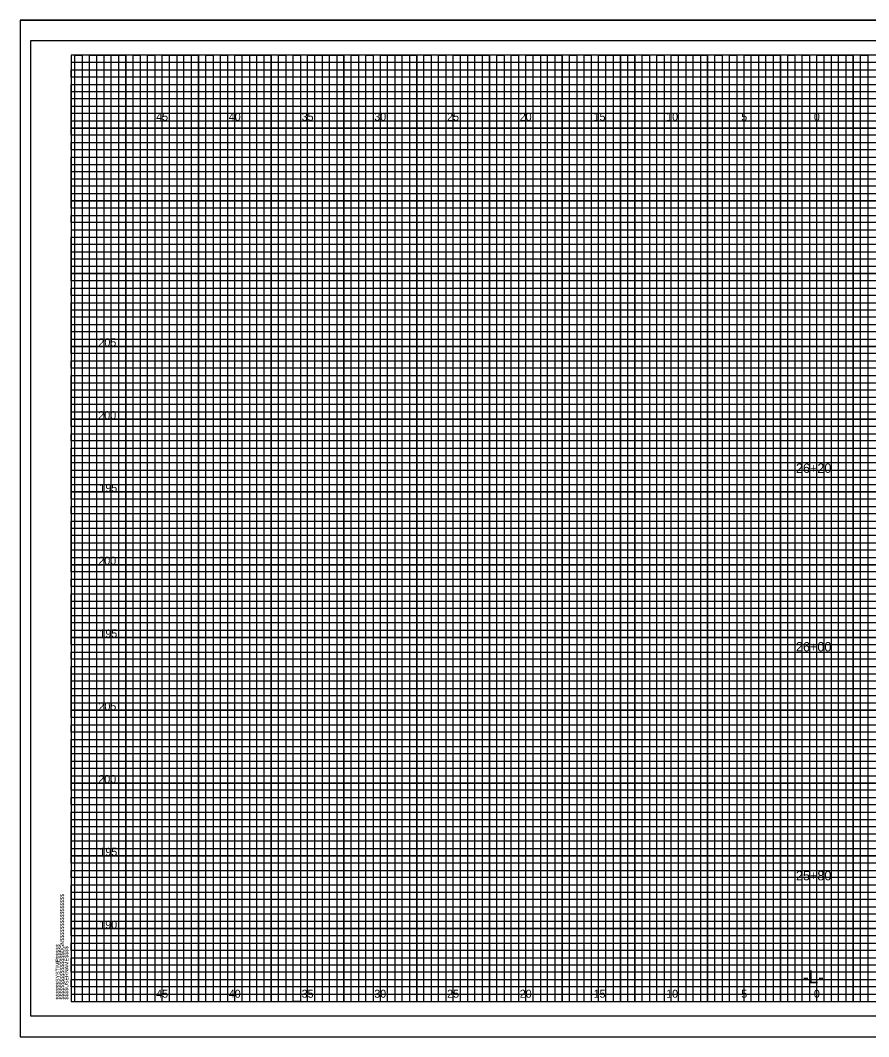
# Model space of a CAD drawing. Extents: x -4 to 103, y -2 to 6583.
# Drawn here: x -3.5 to 54.8, y 1555.7 to 1625.6 of the extents above; entities that cross this region are included whole.
import ezdxf

# ---------------------------------------------------------------- set-up
doc = ezdxf.new("R2010")
doc.units = 0
for name, color, linetype in [('Prop XS Alignment Label', 7, 'Continuous'), ('Prop XS Elevation Labels', 7, 'Continuous'), ('Prop XS Offset Labels', 7, 'Continuous'), ('Prop XS Station Labels', 7, 'Continuous'), ('Sheet Cross Section CELL', 7, 'Continuous'), ('Sheet Cross Section Grid Major CELL', 7, 'Continuous'), ('Sheet Cross Section Grid Middle CELL', 7, 'Continuous'), ('Sheet Cutting Line CELL', 7, 'Continuous'), ('Sheet DOT Grid CELL', 7, 'Continuous'), ('Sheet Plot Border Inside CELL', 7, 'Continuous'), ('Sheet Plot Border Outside CELL', 7, 'Continuous')]:
    doc.layers.add(name, color=color, linetype=linetype)

msp = doc.modelspace()

# ---------------------------------------------------------------- linework, layer by layer
at = {"layer": 'Sheet Cross Section CELL'}
msp.add_lwpolyline([(102.5, 1623.15), (0, 1623.15), (0, 1558.15), (102.5, 1558.15)], close=True, dxfattribs=at)
at = {"layer": 'Sheet Cross Section Grid Major CELL'}
for points in [[(1.25, 1558.15), (1.25, 1623.15), (3.75, 1623.15), (3.75, 1558.15), (6.25, 1558.15), (6.25, 1623.15), (8.75, 1623.15), (8.75, 1558.15), (11.25, 1558.15), (11.25, 1623.15), (13.75, 1623.15), (13.75, 1558.15), (16.25, 1558.15), (16.25, 1623.15), (18.75, 1623.15), (18.75, 1558.15), (21.25, 1558.15), (21.25, 1623.15), (23.75, 1623.15), (23.75, 1558.15), (26.25, 1558.15), (26.25, 1623.15), (28.75, 1623.15), (28.75, 1558.15), (31.25, 1558.15), (31.25, 1623.15), (33.75, 1623.15), (33.75, 1558.15), (36.25, 1558.15), (36.25, 1623.15), (38.75, 1623.15), (38.75, 1558.15), (41.25, 1558.15), (41.25, 1623.15), (43.75, 1623.15), (43.75, 1558.15), (46.25, 1558.15), (46.25, 1623.15), (48.75, 1623.15), (48.75, 1558.15), (51.25, 1558.15), (51.25, 1623.15), (53.75, 1623.15), (53.75, 1558.15)], [(102.5, 1618.15), (0, 1618.15), (0, 1620.65), (74.25, 1620.65)], [(102.5, 1613.15), (0, 1613.15), (0, 1615.65), (102.5, 1615.65)], [(102.5, 1608.15), (0, 1608.15), (0, 1610.65), (102.5, 1610.65)], [(102.5, 1603.15), (0, 1603.15), (0, 1605.65), (102.5, 1605.65)], [(102.5, 1598.15), (0, 1598.15), (0, 1600.65), (102.5, 1600.65)], [(102.5, 1593.15), (0, 1593.15), (0, 1595.65), (102.5, 1595.65)], [(102.5, 1588.15), (0, 1588.15), (0, 1590.65), (102.5, 1590.65)], [(102.5, 1583.15), (0, 1583.15), (0, 1585.65), (102.5, 1585.65)], [(102.5, 1578.15), (0, 1578.15), (0, 1580.65), (102.5, 1580.65)], [(102.5, 1573.15), (0, 1573.15), (0, 1575.65), (102.5, 1575.65)], [(102.5, 1568.15), (0, 1568.15), (0, 1570.65), (102.5, 1570.65)], [(102.5, 1563.15), (0, 1563.15), (0, 1565.65), (102.5, 1565.65)], [(0, 1560.65), (102.5, 1560.65)]]:
    msp.add_lwpolyline(points, dxfattribs=at)
at = {"layer": 'Sheet Cross Section Grid Middle CELL'}
for points in [[(0.25, 1558.15), (0.25, 1623.15), (0.75, 1623.15), (0.75, 1558.15), (1.75, 1558.15), (1.75, 1623.15), (2.25, 1623.15), (2.25, 1558.15), (2.75, 1558.15), (2.75, 1623.15), (3.25, 1623.15), (3.25, 1558.15), (4.25, 1558.15), (4.25, 1623.15), (4.75, 1623.15), (4.75, 1558.15), (5.25, 1558.15), (5.25, 1623.15), (5.75, 1623.15), (5.75, 1558.15), (6.75, 1558.15), (6.75, 1623.15), (7.25, 1623.15), (7.25, 1558.15), (7.75, 1558.15), (7.75, 1623.15), (8.25, 1623.15), (8.25, 1558.15), (9.25, 1558.15), (9.25, 1623.15), (9.75, 1623.15), (9.75, 1558.15), (10.25, 1558.15), (10.25, 1623.15), (10.75, 1623.15), (10.75, 1558.15), (11.75, 1558.15), (11.75, 1623.15), (12.25, 1623.15), (12.25, 1558.15), (12.75, 1558.15), (12.75, 1623.15), (13.25, 1623.15), (13.25, 1558.15), (14.25, 1558.15), (14.25, 1623.15), (14.75, 1623.15), (14.75, 1558.15), (15.75, 1558.15), (15.25, 1558.15), (15.25, 1623.15), (15.75, 1623.15), (15.75, 1558.15), (16.75, 1558.15), (16.75, 1623.15), (17.25, 1623.15), (17.25, 1558.15), (17.75, 1558.15), (17.75, 1623.15), (18.25, 1623.15), (18.25, 1558.15), (19.25, 1558.15), (19.25, 1623.15), (19.75, 1623.15), (19.75, 1558.15), (20.25, 1558.15), (20.25, 1623.15), (20.75, 1623.15), (20.75, 1558.15), (21.75, 1558.15), (21.75, 1623.15), (22.25, 1623.15), (22.25, 1558.15), (22.75, 1558.15), (22.75, 1623.15), (23.25, 1623.15), (23.25, 1558.15), (24.25, 1558.15), (24.25, 1623.15), (24.75, 1623.15), (24.75, 1558.15), (25.25, 1558.15), (25.25, 1623.15), (25.75, 1623.15), (25.75, 1558.15), (26.75, 1558.15), (26.75, 1623.15), (27.25, 1623.15), (27.25, 1558.15), (27.75, 1558.15), (27.75, 1623.15), (28.25, 1623.15), (28.25, 1558.15), (29.25, 1558.15), (29.25, 1623.15), (29.75, 1623.15), (29.75, 1558.15), (30.25, 1558.15), (30.25, 1623.15), (30.75, 1623.15), (30.75, 1558.15)], [(30.75, 1558.15), (31.75, 1558.15), (31.75, 1623.15), (32.25, 1623.15), (32.25, 1558.15), (32.75, 1558.15), (32.75, 1623.15), (33.25, 1623.15), (33.25, 1558.15), (34.25, 1558.15), (34.25, 1623.15), (34.75, 1623.15), (34.75, 1558.15), (35.25, 1558.15), (35.25, 1623.15), (35.75, 1623.15), (35.75, 1558.15), (36.75, 1558.15), (36.75, 1623.15), (37.25, 1623.15), (37.25, 1558.15), (37.75, 1558.15), (37.75, 1623.15), (37.75, 1558.15)], [(38.25, 1623.15), (38.25, 1558.15), (39.25, 1558.15), (39.25, 1623.15), (39.75, 1623.15), (39.75, 1558.15), (40.25, 1558.15), (40.25, 1623.15), (40.75, 1623.15), (40.75, 1558.15), (41.75, 1558.15), (41.75, 1623.15), (42.25, 1623.15), (42.25, 1558.15), (42.75, 1558.15), (42.75, 1623.15), (43.25, 1623.15), (43.25, 1558.15), (43.75, 1558.15), (44.25, 1558.15), (44.25, 1623.15), (44.75, 1623.15), (44.75, 1558.15), (45.25, 1558.15), (45.25, 1623.15), (45.75, 1623.15), (45.75, 1558.15), (46.75, 1558.15), (46.75, 1623.15), (47.25, 1623.15), (47.25, 1558.15), (47.75, 1558.15), (47.75, 1623.15), (48.25, 1623.15), (48.25, 1558.15), (49.25, 1558.15), (49.25, 1623.15), (49.75, 1623.15), (49.75, 1558.15), (50.25, 1558.15), (50.25, 1623.15), (50.75, 1623.15), (50.75, 1558.15), (51.75, 1558.15), (51.75, 1623.15), (52.25, 1623.15), (52.25, 1558.15), (52.75, 1558.15), (52.75, 1623.15), (53.25, 1623.15), (53.25, 1558.15), (54.25, 1558.15), (54.25, 1623.15), (54.75, 1623.15), (54.75, 1558.15), (55.25, 1558.15)], [(0, 1620.15), (0, 1621.15), (74.25, 1621.15), (74.25, 1621.65), (0, 1621.65), (0, 1622.15), (74.25, 1622.15), (74.25, 1622.65), (0, 1622.65)], [(102.5, 1620.15), (0, 1620.15)], [(102.5, 1619.15), (0, 1619.15), (0, 1619.65), (102.5, 1619.65)], [(102.5, 1617.65), (0, 1617.65), (0, 1618.65), (102.5, 1618.65)], [(102.5, 1616.65), (0, 1616.65), (0, 1617.15), (102.5, 1617.15)], [(102.5, 1615.15), (0, 1615.15), (0, 1616.15), (102.5, 1616.15)], [(102.5, 1614.15), (0, 1614.15), (0, 1614.65), (102.5, 1614.65)], [(102.5, 1612.65), (0, 1612.65), (0, 1613.65), (102.5, 1613.65)], [(102.5, 1611.65), (0, 1611.65), (0, 1612.15), (102.5, 1612.15)], [(0, 1611.15), (102.5, 1611.15)], [(102.5, 1610.15), (0, 1610.15)], [(102.5, 1609.15), (0, 1609.15), (0, 1609.65), (102.5, 1609.65)], [(102.5, 1607.65), (0, 1607.65), (0, 1608.65), (102.5, 1608.65)], [(102.5, 1606.65), (0, 1606.65), (0, 1607.15), (102.5, 1607.15)], [(102.5, 1605.15), (0, 1605.15), (0, 1606.15), (102.5, 1606.15)], [(102.5, 1604.15), (0, 1604.15), (0, 1604.65), (102.5, 1604.65)], [(102.5, 1602.65), (0, 1602.65), (0, 1603.65), (102.5, 1603.65)], [(102.5, 1601.65), (0, 1601.65), (0, 1602.15), (102.5, 1602.15)], [(102.5, 1600.15), (0, 1600.15), (0, 1601.15), (102.5, 1601.15)], [(102.5, 1599.15), (0, 1599.15), (0, 1599.65), (102.5, 1599.65)], [(102.5, 1597.65), (0, 1597.65), (0, 1598.65), (102.5, 1598.65)], [(102.5, 1596.65), (0, 1596.65), (0, 1597.15), (102.5, 1597.15)], [(102.5, 1595.15), (0, 1595.15), (0, 1596.15), (102.5, 1596.15)], [(102.5, 1594.15), (0, 1594.15), (0, 1594.65), (102.5, 1594.65)], [(102.5, 1592.65), (0, 1592.65), (0, 1593.65), (102.5, 1593.65)], [(102.5, 1591.65), (0, 1591.65), (0, 1592.15), (102.5, 1592.15)], [(102.5, 1590.15), (0, 1590.15), (0, 1591.15), (102.5, 1591.15)], [(102.5, 1589.15), (0, 1589.15), (0, 1589.65)], [(0, 1589.65), (102.5, 1589.65)], [(102.5, 1587.65), (0, 1587.65), (0, 1588.65), (102.5, 1588.65)], [(102.5, 1586.65), (0, 1586.65), (0, 1587.15), (102.5, 1587.15)], [(102.5, 1585.15), (0, 1585.15), (0, 1586.15), (102.5, 1586.15)], [(102.5, 1584.15), (0, 1584.15), (0, 1584.65), (102.5, 1584.65)], [(102.5, 1582.65), (0, 1582.65), (0, 1583.65), (102.5, 1583.65)], [(102.5, 1581.65), (0, 1581.65), (0, 1582.15), (102.5, 1582.15)], [(102.5, 1580.15), (0, 1580.15), (0, 1581.15), (102.5, 1581.15)], [(102.5, 1579.15), (0, 1579.15), (0, 1579.65), (102.5, 1579.65)], [(102.5, 1577.65), (0, 1577.65), (0, 1578.65), (102.5, 1578.65)], [(102.5, 1576.65), (0, 1576.65), (0, 1577.15), (102.5, 1577.15)], [(102.5, 1575.15), (0, 1575.15), (0, 1576.15), (102.5, 1576.15)], [(102.5, 1574.15), (0, 1574.15), (0, 1574.65), (102.5, 1574.65)], [(102.5, 1572.65), (0, 1572.65), (0, 1573.65), (102.5, 1573.65)], [(102.5, 1571.65), (0, 1571.65), (0, 1572.15), (102.5, 1572.15)], [(102.5, 1570.15), (0, 1570.15), (0, 1571.15), (102.5, 1571.15)], [(102.5, 1569.15), (0, 1569.15), (0, 1569.65), (102.5, 1569.65)], [(102.5, 1567.65), (0, 1567.65), (0, 1568.65), (102.5, 1568.65)], [(102.5, 1566.65), (0, 1566.65), (0, 1567.15), (102.5, 1567.15)], [(102.5, 1565.15), (0, 1565.15), (0, 1566.15), (102.5, 1566.15)], [(102.5, 1564.15), (0, 1564.15), (0, 1564.65), (102.5, 1564.65)], [(102.5, 1562.65), (0, 1562.65), (0, 1563.65), (102.5, 1563.65)], [(102.5, 1561.65), (0, 1561.65), (0, 1562.15), (102.5, 1562.15)], [(102.5, 1560.15), (0, 1560.15), (0, 1561.15), (102.5, 1561.15)], [(102.5, 1559.15), (0, 1559.15), (0, 1559.65), (102.5, 1559.65)], [(0, 1558.65), (102.5, 1558.65)]]:
    msp.add_lwpolyline(points, dxfattribs=at)
at = {"layer": 'Sheet Cutting Line CELL'}
for p, q in [((-3.5, 1625.55), (103.4, 1625.55)), ((-3.5, 1625.55), (-3.5, 1555.725)), ((-3.5, 1555.725), (103.4, 1555.725))]:
    msp.add_line(p, q, dxfattribs=at)
at = {"layer": 'Sheet DOT Grid CELL'}
for p, q in [((1.25, 1558.15), (1.25, 1623.15)), ((3.75, 1558.15), (3.75, 1623.15)), ((6.25, 1558.15), (6.25, 1623.15)), ((8.75, 1558.15), (8.75, 1623.15)), ((11.25, 1558.15), (11.25, 1623.15)), ((13.75, 1558.15), (13.75, 1623.15)), ((16.25, 1558.15), (16.25, 1623.15)), ((18.75, 1558.15), (18.75, 1623.15)), ((21.25, 1558.15), (21.25, 1623.15)), ((23.75, 1558.15), (23.75, 1623.15)), ((26.25, 1558.15), (26.25, 1623.15)), ((28.75, 1558.15), (28.75, 1623.15)), ((31.25, 1558.15), (31.25, 1623.15)), ((33.75, 1558.15), (33.75, 1623.15)), ((36.25, 1558.15), (36.25, 1623.15)), ((38.75, 1558.15), (38.75, 1623.15)), ((41.25, 1558.15), (41.25, 1623.15)), ((43.75, 1558.15), (43.75, 1623.15)), ((46.25, 1558.15), (46.25, 1623.15)), ((48.75, 1558.15), (48.75, 1623.15)), ((51.25, 1558.15), (51.25, 1623.15)), ((53.75, 1558.15), (53.75, 1623.15)), ((0, 1620.65), (74.25, 1620.65)), ((0, 1618.15), (102.5, 1618.15)), ((0, 1615.65), (102.5, 1615.65)), ((0, 1613.15), (102.5, 1613.15)), ((0, 1610.65), (102.5, 1610.65)), ((0, 1608.15), (102.5, 1608.15)), ((0, 1605.65), (102.5, 1605.65)), ((0, 1603.15), (102.5, 1603.15)), ((0, 1600.65), (102.5, 1600.65)), ((0, 1598.15), (102.5, 1598.15)), ((0, 1595.65), (102.5, 1595.65)), ((0, 1593.15), (102.5, 1593.15)), ((0, 1590.65), (102.5, 1590.65)), ((0, 1588.15), (102.5, 1588.15)), ((0, 1585.65), (102.5, 1585.65)), ((0, 1583.15), (102.5, 1583.15)), ((0, 1580.65), (102.5, 1580.65)), ((0, 1578.15), (102.5, 1578.15)), ((0, 1575.65), (102.5, 1575.65)), ((0, 1573.15), (102.5, 1573.15)), ((0, 1570.65), (102.5, 1570.65)), ((0, 1568.15), (102.5, 1568.15)), ((0, 1565.65), (102.5, 1565.65)), ((0, 1563.15), (102.5, 1563.15)), ((0, 1560.65), (102.5, 1560.65))]:
    msp.add_line(p, q, dxfattribs=at)
at = {"layer": 'Sheet Plot Border Inside CELL'}
msp.add_lwpolyline([(103, 1624.15), (-2.8, 1624.15), (-2.8, 1557.15), (103, 1557.15)], close=True, dxfattribs=at)
at = {"layer": 'Sheet Plot Border Outside CELL'}
msp.add_lwpolyline([(103.4, 1625.55), (-3.5, 1625.55), (-3.5, 1555.725), (103.4, 1555.725)], close=True, dxfattribs=at)

# ---------------------------------------------------------------- texts
at = {"layer": 'Prop XS Alignment Label'}
msp.add_text('-L-', height=0.875, dxfattribs=at).set_placement((50.307, 1559.4))
at = {"layer": 'Prop XS Elevation Labels'}
for s, p in [('205', (1.872, 1603.15)), ('200', (1.864, 1598.15)), ('195', (1.938, 1593.15)), ('200', (1.864, 1588.15)), ('195', (1.938, 1583.15)), ('205', (1.872, 1578.15)), ('200', (1.864, 1573.15)), ('195', (1.938, 1568.15)), ('190', (1.93, 1563.15))]:
    msp.add_text(s, height=0.55, dxfattribs=at).set_placement(p)
at = {"layer": 'Prop XS Offset Labels'}
for s, p in [('45', (5.84, 1618.65)), ('40', (10.831, 1618.65)), ('35', (15.84, 1618.65)), ('30', (20.831, 1618.65)), ('25', (25.84, 1618.65)), ('20', (30.831, 1618.65)), ('15', (35.906, 1618.65)), ('10', (40.897, 1618.65)), ('5', (46.057, 1618.65)), ('0', (51.049, 1618.65)), ('0', (51.049, 1618.65)), ('45', (5.84, 1558.4)), ('40', (10.831, 1558.4)), ('35', (15.84, 1558.4)), ('30', (20.831, 1558.4)), ('25', (25.84, 1558.4)), ('20', (30.831, 1558.4)), ('15', (35.906, 1558.4)), ('10', (40.897, 1558.4)), ('5', (46.057, 1558.4)), ('0', (51.049, 1558.4)), ('0', (51.049, 1558.4))]:
    msp.add_text(s, height=0.55, dxfattribs=at).set_placement(p)
at = {"layer": 'Prop XS Station Labels'}
for s, p in [('26+20', (49.816, 1594.457)), ('26+00', (49.816, 1582.189)), ('25+80', (49.816, 1566.464))]:
    msp.add_text(s, height=0.65, dxfattribs=at).set_placement(p)
at = {"layer": 'Sheet Cross Section CELL'}
for s, p in [('$$$$$$$$$$$$$$$$DGN$$$$$$$$$$$$$$$$', (-0.5, 1558.275)), ('$$$$$$SYSTIME$$$$$', (-0.797, 1558.275)), ('$$$$USERNAME$$$$', (-0.2, 1558.275))]:
    msp.add_text(s, height=0.2625, rotation=90, dxfattribs=at).set_placement(p)
at = {"layer": 'Sheet Cross Section Grid Major CELL'}
msp.add_text('040397', height=0.0025, rotation=90, dxfattribs=at).set_placement((-0.001, 1623.136))

doc.saveas('drawing.dxf')
